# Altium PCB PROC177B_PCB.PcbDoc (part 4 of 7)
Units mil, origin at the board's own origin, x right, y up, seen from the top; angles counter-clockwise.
Board outline 4257.98 x 1561.15 mil, 4 copper layers (Top Layer, Int1 (GND), Int2 (PWR), Bottom Layer), stack 63.572 mil thick; 461 components, 307 nets, 1564 pads, 607 vias.
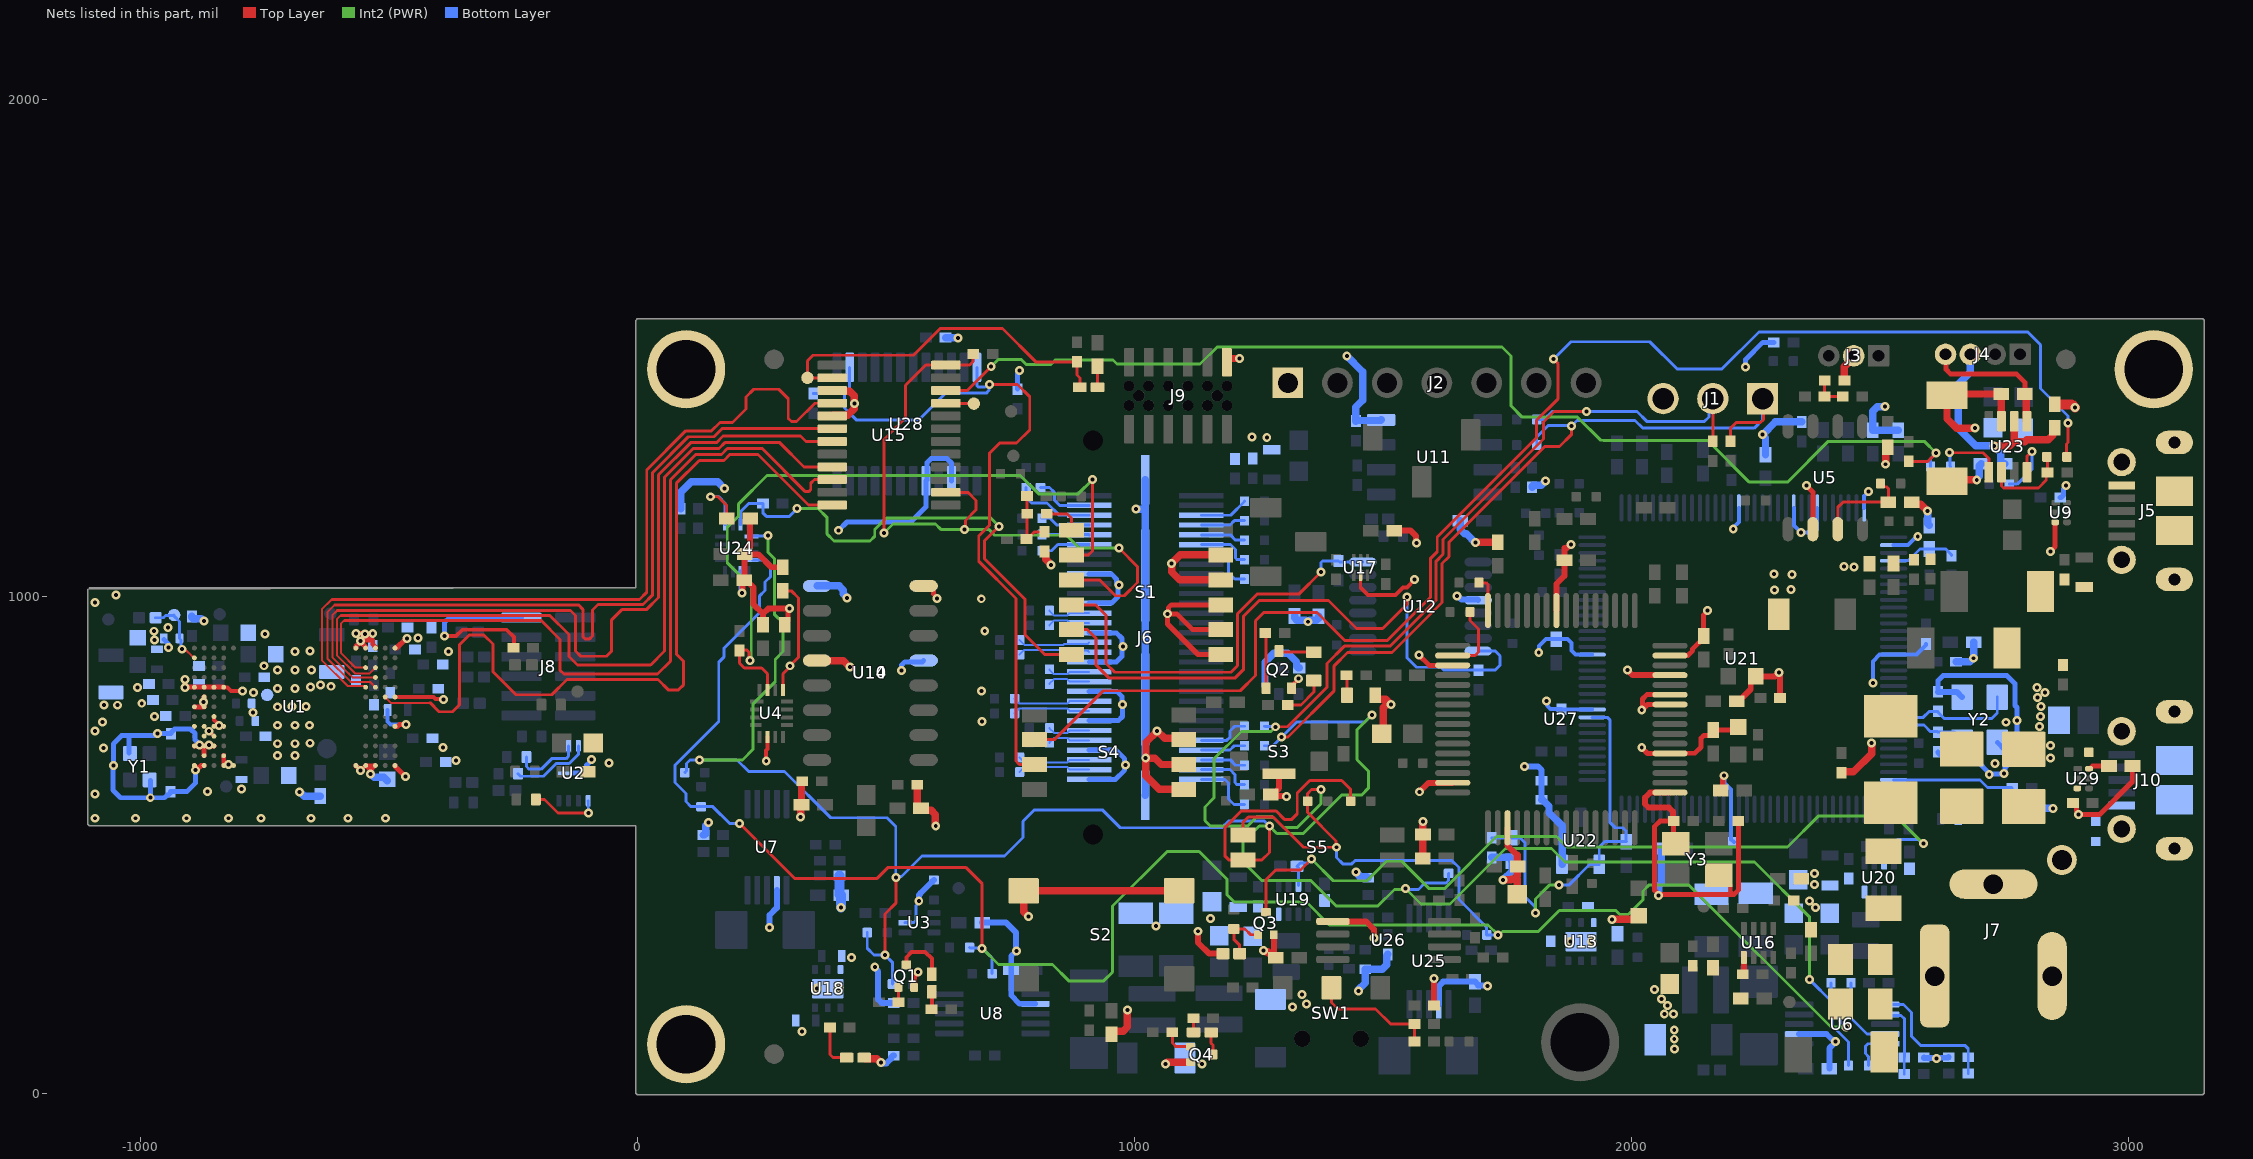
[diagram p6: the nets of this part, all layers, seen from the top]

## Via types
v1: diameter 18, hole 8, Top Layer to Bottom Layer, tented both sides, 603 vias
v2: diameter 19.68, hole 7.87, Top Layer to Bottom Layer, 4 vias

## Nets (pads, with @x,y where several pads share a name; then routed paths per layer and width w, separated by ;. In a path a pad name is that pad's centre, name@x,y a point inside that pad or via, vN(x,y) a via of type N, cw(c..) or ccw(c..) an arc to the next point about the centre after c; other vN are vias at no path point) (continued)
GND: C2.2 C3.1 C4.1 C5.1 C6.2 C7.1 C8.1 C9.1 C10.1 C11.1 C12.1 C13.2 C14.1 C15.2 C16.1 C17.1 C18.1 C19.1 C20.1 C21.1 C22.1 C23.2 C24.1 C25.1 C26.1 C27.1 C28.1 C29.1 C30.2 C31.2 C32.1 C33.1 C34.2 C35.1 C36.2 C37.1 C38.1 C39.1 C40.2 C41.2 C42.2 C43.2 C44.2 C45.2 C46.1 C47.2 C48.2 C49.2 C50.1 C51.2 C52.1 C53.2 C55.2 C56.2 C57.2 C58.2 C59.2 C60.1 C61.1 C62.2 C63.2 C65.2 C66.2 C67.2 C68.1 C69.1 C70.1 C72.2 C73.2 C74.2 C75.2 C79.1 C84.2 C85.1 C86.1 C88.2 C89.2 C90.2 C91.2 C92.2 C93.2 C94.2 C95.1 C96.1 C97.1 C98.1 C99.1 C101.1 C102.1 C105.1 C106.1 C108.2 C113.1 C114.2 C115.2 C116.1 C118.1 C119.2 C120.2 C121.1 C122.1 C123.2 C124.1 C125.1 C126.1 C127.2 C128.2 C129.2 C130.1 C131.1 C132.2 C133.2 C134.2 C135.2 C136.2 C137.2 C138.2 C139.2 C140.2 C141.2 C142.1 C143.2 C144.2 C145.2 C146.1 C147.2 C148.2 C149.1 C150.2 C151.1 C152.2 C153.2 C157.2 C158.2 D4.2 D6.2 D10.2 J1.3 J2.1 J3.2 J4.4 J5.5 J5.6 J5.7 J5.8 J5.9 J5.10 J5.11 J6.18 J6.24 J6.30 J6.36 J6.42 J6.48 J6.54 J6.60 J6.MP1 J6.MP2 J6.MP3 J6.MP4 J7.2 J7.3 J8.11 J9.12 J10.5 pad.TH1 pad.TH4 pad.TH9 Q1.2 Q2.2 Q3.2 Q4.2 R6.1 R10.2 R11.1 R33.1 R36.1 R57.2 R71.1 R72.1 R83.1 R91.2 R101.1 R103.1 R113.1 R114.1 R116.1 R117.1 R120.1 R121.1 R148.1 R150.1 R152.2 R158.1 R162.1 R177.1 R178.1 R180.1 R191.2 R194.2 R201.1 R205.1 R208.1 R215.2 R218.1 R234.1 R239.1 R260.1 R261.1 S1.7 S1.8 S1.9 S1.10 S1.11 S2.1 S2.2 S3.5 S4.5 S4.6 S4.7 TP7.1 TP11.1 U1.A1 U1.A3 U1.A4 U1.A5 U1.A6 U1.A7 U1.A9 U1.A10 U1.B7 U1.B9 U1.C8 U1.C9 U1.C10 U1.D8 U1.D9 U1.E1 U1.E7 U1.E8 U1.E9 U1.E10 U1.F8 U1.G9 U1.G10 U1.H1 U1.H9 U1.J7 U1.J8 U1.J9 U1.J10 U1.N1 U1.N3 U1.N4 U1.N5 U2.4 U2.9 U3.2 U4.6 U5.2 U6.7 U7.7 U8.7 U9.3 U10.8 U10.12 U11.4 U12.4 U13.3 U13.7@1898.8,304.92 U14.8 U14.12 U15.3 U15.5 U16.1 U17.2 U18.3 U18.7@383.33,210.5 U19.8 U20.8 U21.10 U21.17 U21.48 U21.55 U21.58 U21.64 U21.66 U21.80 U21.114 U22.2 U23.5 U24.6 U25.7 U26.5 U27.1 U27.5 U27.10 U27.11 U27.13 U27.15 U27.25 U27.35 U27.47 U27.51 U28.3 U28.5 U29.3 Y1.2 Y1.4 Y2.2 Y2.4 Y3.2 Y3.4 | length 14542.7
  Top Layer w5.9: U17.2@1455.43,1041.94 1455.43,1017.67 1456.22,1016.88
  Top Layer w8: v1(-861.2,728.31) U1.D8@-851.36,718.46 ; U1.F8@-851.36,757.83 -851.36,750.77 -841.52,740.92 v1(-841.52,739.83) -840.18,738.5 -832.03,738.5 U1.E7@-831.67,738.15 ; U1.J7@-831.67,816.89 -831.32,816.54 -824.42,816.54 -817.04,809.16 v1(-793.68,809.16) ; v1(-556.53,649.12) U1.A4@-546.24,659.41 ; U1.H1@-487.19,797.2 -409.65,797.2 -405.69,793.25 -390.42,793.25 v1(-389.2,792.03) ; v1@-387.87,917.47 v1(-387.87,919.64) -364.47,919.64 -351.62,932.49 -263.18,932.49 -248.11,917.42 C60.1@-248.11,897.01 ; v1(259.69,668.14) 259.58,668.25 259.58,689.74 261.97,692.13 U4.6@261.97,716.92 ; Q2.2@1316.5,814.83 1321.75,820.08 1321.75,824.25 1329.98,832.47 v1(1329.98,833.94) ; 1456.22,1016.88 1470.64,1002.46 1525.86,1002.46 1540.96,1017.56 1548.51,1017.56 v1(1564.15,1033.2) ; Y3.2@2176,438.61 2179.94,438.61 2199.56,418.99 2199.56,406.22 2206.17,399.6 ; U1.A4@-546.24,659.41 -546.24,658.91 -538.26,650.93 -538.26,644.01 v1(-536.35,642.1) -534.43,644.01 -534.43,651.03 -526.56,658.91 U1.A3@-526.56,659.41 U1.A4@-546.24,659.41
  Top Layer w10: v1(-909.63,816.66) v1(-909.63,832.61) v1@-909.63,833.61 ; v1@-907.96,816.89 U1.J10@-890.73,816.89 U1.J9@-871.04,816.89 U1.J8@-851.36,816.89 U1.J7@-831.67,816.89 ; U1.A10@-890.73,659.41 -889.45,658.13 -889.45,651 v1(-888.3,649.85) -886.68,649.85 -877.12,659.41 U1.A9@-871.04,659.41 ; U1.G10@-890.73,777.52 U1.G9@-872.73,777.52 ; U1.C10@-887.52,699.03 -890.48,699.03 U1.C10@-890.73,698.78 U1.C9@-871.04,698.78 ; U1.B9@-871.04,679.09 U1.C9@-871.04,698.78 ; U1.G9@-871.04,777.52 -871.58,778.06 -871.58,786.21 v1(-872.73,787.36) -871.58,788.51 -871.58,796.67 U1.H9@-871.04,797.2 ; U1.C8@-851.36,698.78 U1.C9@-871.04,698.78 ; U1.A7@-831.67,659.41 U1.B7@-831.67,679.09 ; U1.A5@-565.93,659.41 -556.53,650.01 v1(-556.53,649.12) ; U1.N5@-565.93,895.63 -565.93,898.72 v1@-557.22,907.43 ; v1(-565.95,925.04) -565.53,924.62 -548.35,924.62 v1(-547.94,924.2) -547.94,922.58 -544.91,919.56 -544.91,919.49 -536.8,911.38 ; v1@-558.07,907.43 v1@-557.22,907.43 ; v1(-556.55,909.72) -556.55,908.09 v1@-557.22,907.43 ; -547.09,911.38 -536.8,911.38 ; U1.N4@-546.24,895.63 -546.24,897.78 -555.89,907.43 v1@-557.22,907.43 ; -532.41,911.38 -536.8,911.38 ; -531.91,911.38 -531.91,903.25 -526.56,897.89 U1.N3@-526.56,895.63 ; U1.A1@-487.19,659.41 -487.19,657.88 -466.92,637.61 v1(-465.65,637.61) ; U1.E1@-487.19,738.15 -481.89,738.15 -478.61,741.43 -465.08,741.43 v1(-464.61,741.9) ; U1.N1@-487.19,895.63 -483.99,895.63 -465.61,914.01 -463.89,914.01 v1(-462.74,915.16) ; C40.2@296.84,942.57 303.65,949.38 303.65,969.86 306.55,972.77 v1(306.55,974.93) ; U14.8@576.39,1020.53 589.44,1020.53 595.73,1014.24 595.73,1004.78 602.81,997.7 v1(602.81,995.53) ; S1.7@1173.96,882.62 1128.38,882.62 1067,944 v1(1067,964.6) ; S1.8@1173.96,932.62 1117.38,932.62 1085.55,964.45 1067.15,964.45 v1(1067,964.6) ; S1.9@1173.96,982.62 1074.64,982.62 1068.53,976.5 1068.53,966.13 v1(1067,964.6) ; v1(1572.8,881.36) 1593.32,860.84 U27.35@1640.61,860.84 ; v1(2020.94,695.16) 2032.44,683.67 U27.5@2077.62,683.67 2077.96,684.02 2127.65,684.02 2140.31,696.68 2140.31,714.24 2146.17,720.1 2157.93,720.1 2164.74,726.91 C142.1@2164.74,730.84 2208.84,730.84 C141.2@2214.74,736.75 ; v1(2020.94,770.6) v1@2022.44,772.1 ; U27.10@2077.62,782.1 2032.44,782.1 v1@2022.44,772.1 ; U27.11@2077.62,801.78 2031.18,801.78 2022.44,793.04 v1@2022.44,772.1 ; U27.15@2077.62,880.52 2077.96,880.87 2113.93,880.87 2123.39,890.33 2123.39,893.92 2145.41,915.94 C140.2@2145.41,919.88 2145.41,962.63 v1(2153.65,970.87) ; Y3.4@2089.38,501.6 2085.23,505.75 C148.2@2085.23,547.51 2057.66,547.51 2047.03,536.88 2047.03,408.16 2055.06,400.13 v1(2055.06,398.3) 2056.36,399.6 2206.17,399.6 2215.12,408.54 C147.2@2215.12,547.51 ; v1(2352,1222.6) 2365.27,1209.33 U5.2@2365.27,1134.88 ; J4.4@2632.04,1486.59 2633.21,1485.42 2633.21,1455.92 2642.38,1446.75 2775.16,1446.75 2791.62,1430.29 C123.2@2791.62,1406.74 ; v1(2843,1089.6) 2843,1089.74 2852.72,1099.46 U9.3@2852.72,1148.57 ; R260.1@2888.29,584.07 2890.26,584.07 2895.1,579.23 2895.1,567.49 2899.47,563.12 v1(2899.47,560.95) 2941.95,560.95 3008.27,627.27 C158.2@3008.27,658.22
  Top Layer w12: v1(210.65,1006.68) 211.8,1007.83 211.8,1028.39 C2.2@215.41,1032 ; R33.1@227.35,1156.14 227.35,1097.45 225.9,1096 225.9,1090.42 220.09,1084.61 C56.2@216.15,1084.61 ; C91.2@253.09,942.57 253.09,964.32 ; R6.1@293,1058.22 269.93,1058.22 244.42,1083.73 217.03,1083.73 C56.2@216.15,1084.61 ; v1(306.55,974.93) 263.7,974.93 253.09,964.32 ; Q1.2@557.18,212.97 557.18,235.84 565.26,243.91 v1(565.26,244.19) ; v1(1128.09,325.95) 1128.09,303.33 1150.55,280.87 R177.1@1178.5,280.87 ; C138.2@1281.06,276.91 Q3.2@1281.06,318.65 ; S3.5@1291.37,642.9 1291.37,613.97 1278.24,600.84 R215.2@1274.3,600.84 1276.99,598.15 1305.42,598.15 v1(1306.56,597) ; U26.5@1399.58,345.78 1466.13,345.78 1481.98,329.94 v1(1481.98,311.94) ; C52.1@1522.83,1131.87 1556.02,1131.87 1566.59,1121.31 1566.59,1107.8 v1(1567.74,1106.65) ; v1(1573.94,606.54) 1592.01,624.62 U27.47@1640.61,624.62 ; v1(1602.6,230.66) 1602.85,230.41 1602.85,176.85 R205.1@1603.1,176.6 ; U27.51@1750.84,534.06 1750.94,533.97 1750.94,498.09 1770.18,478.84 ; C150.2@1770.18,457.3 C150.2@1771.42,456.06 ; U27.25@1849.27,971.07 1849.27,1024.64 1865.44,1040.8 C153.2@1865.44,1072.47 1865.44,1097.27 1870.24,1097.27 1876.86,1103.9 v1(1878.49,1103.9) ; v1(1992,851.6) 2002.45,841.15 U27.13@2077.62,841.15 ; U27.1@2077.62,604.93 2077.52,604.84 2037.54,604.84 2027.38,594.68 2027.38,581.89 2034.45,574.82 2075.53,574.82 2083.69,566.66 2083.69,549.05 C148.2@2085.23,547.51 ; C106.1@2179.82,608.87 2183.9,612.95 2183.9,634.27 2186.8,637.17 v1(2186.8,638.8) ; C146.1@2212.15,788.54 2216.09,788.54 2240.2,812.65 2240.2,829.1 C145.2@2249.95,838.85 2288.62,838.85 v1(2296.66,846.89) 2296.66,845.26 2299.28,842.64 R218.1@2299.28,794.95 ; C136.2@2224.31,239.6 2226.38,241.67 2226.38,273.37 U16.1@2226.47,273.47 ; C2.2@215.41,1032 219.35,1032 234.34,1017.01 234.34,983.06 253.09,964.32 ; C2.2@215.41,1032 216.15,1032.74 215.78,1033.11 215.78,1084.24 C56.2@216.15,1084.61
  Top Layer w15: v1(328.94,555.46) 329.51,556.04 329.51,579.22 C89.2@330.57,580.27 330.57,626.49 C90.2@331.88,627.8 ; U14.12@361.83,870.53 414.26,870.53 427.19,857.6 v1(428,857.6) ; U15.5@392.51,1362.51 393.87,1363.87 423.2,1363.87 436.46,1377.14 436.46,1387.03 v1(437.03,1387.6) ; U15.3@392.51,1413.69 393.87,1412.34 427.67,1412.34 436.46,1403.55 v1@436.46,1388.06 ; D6.2@456.79,71.69 459.14,69.35 482.1,69.35 489.37,62.08 v1(490.18,62.08) ; C88.2@563.4,620.74 563.4,577.86 567.71,573.55 C75.2@570.88,573.55 575.19,569.24 591.32,569.24 600.11,560.45 600.11,538.15 v1(600.68,537.57) ; v1(787,355.6) 777.5,365.1 S2.1@777.5,407.18 S2.2@1090.49,407.18 ; R208.1@819.66,1090.02 822,1087.68 822,1074.04 832.18,1063.86 v1(832.18,1063.05) ; C53.2@954.88,121.37 958.31,124.8 977.56,124.8 986.34,133.59 v1@986.34,166.55 ; v1(1062.6,58.83) 1063.41,58.83 1066.83,62.25 Q4.2@1113.28,62.25 ; v1(1075.32,1065.6) 1075.32,1048.68 1091.38,1032.62 S1.10@1173.96,1032.62 ; v1@1075.62,1065.9 1092.72,1083 1173.57,1083 S1.11@1173.96,1082.62 ; S4.5@1099.68,611.36 1050.31,611.36 1023.1,638.58 v1(1023.1,674.39) ; S4.6@1099.68,661.36 1054.14,661.36 1041.68,673.82 1023.68,673.82 v1(1023.1,674.39) ; S4.7@1099.68,711.36 1096.59,714.45 1060.97,714.45 1046.81,728.6 v1(1046,728.6) 1023.68,706.28 1023.68,674.97 v1(1023.1,674.39) ; J9.12@1186.47,1476.71 1187.9,1478.15 v1(1212.01,1478.15) ; v1(1260.17,287.48) 1260.98,287.48 1264.04,284.41 1268.63,284.41 1276.13,276.91 1280.07,276.91 C138.2@1284.38,272.6 ; D10.2@1484.95,800.77 1484.95,796.83 1489.26,792.52 1505.79,792.52 v1@1511.7,786.61 ; C151.1@1497.62,723.04 1500.67,726.1 1500.67,775.58 v1@1511.7,786.61 ; v1(1516.26,782.05) v1@1511.7,786.61 ; v1(1580.68,546.28) v1(1580.68,546.28) 1580.73,520.82 C143.2@1580.78,520.77 1580.7,520.69 C144.2@1580.7,472.42 ; v1(1686.78,1107.74) 1687.59,1107.74 1688.17,1108.32 C152.2@1731.16,1108.32 ; v1(1742.05,429.4) 1742.62,429.98 1757.84,429.98 1758,430.13 1770.07,430.13 C149.1@1770.07,400.73 ; C150.2@1770.18,457.3 1770.18,478.84 ; 1770.74,436.17 1770.74,455.39 C150.2@1771.42,456.06 ; v1(1961.35,349.63) 1961.92,350.2 2008.07,350.2 C139.2@2015.1,357.24 ; C108.2@2425,644.92 2426.58,646.5 2446.89,646.5 2483.27,682.88 v1(2483.27,704.22) ; C39.1@2428.68,1433.6 2428.68,1461.7 2446.72,1479.73 J3.2@2446.72,1483.05 ; v1(2511.14,1265.41) 2511.71,1265.99 2511.71,1295.86 C38.1@2515.6,1299.75 ; C37.1@2564.2,1189.11 2568.51,1184.8 2582.47,1184.8 v1@2595.01,1172.26 ; C123.2@2791.62,1406.74 2794.52,1403.84 2794.52,1352.96 U23.5@2795.88,1351.6
  Top Layer w20: C132.2@2851.75,1386.02 2885.9,1386.02 v1(2892.5,1379.42)
  Bottom Layer w5.9: U3.2@538.95,343.01 539.83,343.88 556.75,343.88 561,348.13 561,377.8 566.53,383.33 v1(566.53,386.58)
  Bottom Layer w8: C17.1@-501.85,770.72 -501.85,747.52 -495.76,741.43 -465.08,741.43 v1(-464.61,741.9) ; U24.6@208.28,1049.18 208.28,1011.76 210.65,1009.39 v1(210.65,1006.68) ; v1(1813.74,886.39) 1814.43,887.08 1814.43,899.41 1828.64,913.62 C116.1@1848.96,913.62 1871.95,913.62 1879.81,905.76 1879.81,890.35 1887.77,882.39 U21.17@1921.25,882.32 U21.17@1921.25,882.32 ; v1(1829.35,789.39) 1831.26,787.48 1831.26,778.78 1837.47,772.58 C115.2@1859.31,772.58 ; C115.2@1859.8,772.09 U21.10@1921.25,772.09 ; v1(2186.8,638.8) 2187.8,637.8 2187.8,624.2 2200.78,611.22 U21.114@2200.78,571.3 U21.114@2200.78,571.3 2200.84,510.99 C127.2@2206.38,505.45 ; v1(2205,1135.24) 2205,1137.95 2216.46,1149.41 2216.46,1177.54 U21.48@2216.52,1177.6 ; U21.55@2326.76,1177.6 2326.76,1142.34 v1(2341.3,1127.81) 2367.78,1127.81 2374,1134.03 U21.58@2374,1177.6 ; U21.64@2468.49,1177.6 2468.49,1201.1 2477.04,1209.65 v1(2477.04,1210.93) ; v1(2485.7,825.75) 2485.7,868.39 2499.63,882.32 U21.80@2527.55,882.32 2573.49,882.32 2592.89,901.72 C114.2@2592.89,903.69 ; U21.66@2527.55,1102.8 2527.61,1102.86 2556.26,1102.86 2573.85,1120.45 v1(2576.18,1120.45)
  Bottom Layer w10: Y1.2@-1022.21,684.49 -1022.21,718.84 ; Y1.4@-978.9,629.37 -979.18,629.09 -979.18,594.81 v1(-979.47,594.53) ; C3.1@-952.26,913.14 -944.15,905.03 -944.15,898.45 v1(-942.62,896.92) ; v1(-888.3,649.85) -888.3,624.35 -905.99,606.66 C33.1@-938.64,606.66 -938.64,604.7 -943.49,599.85 -945.46,599.85 -950.78,594.53 v1(-979.47,594.53) ; v1@-880.46,698.7 -880.46,701.76 -889.27,710.57 -889.27,723.62 -898.55,732.89 -930.43,732.89 -937.91,725.42 C32.1@-937.91,723.45 -938.43,723.97 v1(-965.07,723.97) -966.69,723.97 -971.37,719.29 -1037.34,719.29 -1053.85,702.79 v1(-1053.85,659.78) -1054.79,658.84 -1054.79,609.98 -1039.34,594.53 v1(-979.47,594.53) ; v1(-387.87,919.64) -387.47,920.03 -387.47,947.64 -378.23,956.88 J8.11@-232.85,956.88 ; U2.9@-128.06,643.83 -102.63,643.83 -101.56,644.89 -101.56,659.95 -91.45,670.07 v1(-91.45,671.69) ; v1(404.9,1132.6) 405.71,1132.6 422.19,1149.07 550.46,1149.07 581.03,1179.65 U28.5@581.03,1232.02 583.04,1234.03 583.04,1268.47 591.17,1276.6 623.42,1276.6 632.21,1267.82 U28.3@632.21,1232.02 ; v1(532,850.6) 532,861.6 538.32,867.92 573.79,867.92 U10.12@576.39,870.53 ; R91.2@765.35,1416.41 765.35,1448.12 768.78,1451.55 v1(768.78,1453.71) ; J6.60@909.41,631.37 962.06,631.37 980.64,649.95 980.64,658.82 v1@980.78,658.96 ; J6.54@909.41,690.42 963,690.42 980.65,672.77 980.65,659.09 v1@980.78,658.96 ; J6.48@909.41,749.48 968.02,749.48 976.37,757.83 976.37,781.53 v1(976.67,781.83) 975.14,783.36 975.14,798.46 965.07,808.53 J6.42@909.41,808.53 ; J6.30@909.41,926.64 909.91,926.15 964.04,926.15 975.45,914.74 975.45,899.59 v1@976.47,898.56 ; J6.24@909.41,985.7 909.91,986.19 954.54,986.19 967.57,999.22 967.57,1021.22 v1(969.1,1022.75) ; J6.18@909.41,1044.75 909.91,1044.26 954.54,1044.26 964.1,1034.7 v1@964.1,1023.15 ; J6.36@909.57,867.75 964.1,867.75 975.45,879.1 975.45,897.03 v1(976.98,898.56) ; v1@981,658.74 v1@980.78,658.96 ; v1(982.17,660.35) v1@980.78,658.96 ; v1(2230,1460.62) 2230,1476.11 2264.4,1510.51 R71.1@2286.59,1510.51 ; C97.1@2616.98,687.07 2616.98,685.1 2621.82,680.26 2630.97,680.26 2647.89,663.34 2700.73,663.34 2707.8,656.27 2707.8,655.97 2720,643.77 v1(2720,641.6) 2720.92,642.52 2749.08,642.52 v1(2750,643.44) 2751.53,644.97 2751.53,655.5 2775.84,679.81 ; C98.1@2616.98,807.64 2616.98,829.96 2627.42,840.41 2755.33,840.41 2771.86,823.88 2771.86,779.98 2775.84,776 v1(2775.84,749.99) 2775.84,679.81 ; Y2.2@2736.13,705.86 2752.78,689.2 2766.44,689.2 2775.84,679.81 ; R72.1@2862.68,1198.6 2864.65,1198.6 2869.49,1203.44 2869.49,1215.73 2874.5,1220.73 v1(2874.5,1222.89)
  Bottom Layer w11: v1(762.76,286.62) 752.17,276.03 C59.2@752.17,249.69 752.17,197.42 769.58,180 800.87,180 U8.7@801.28,179.6
  Bottom Layer w12: v1(266.67,333.78) 266.67,358.69 280.99,373.01 U7.7@280.99,408.58 ; v1(478,253.6) 478,251.98 484.7,245.28 484.7,188.63 491.73,181.6 R116.1@516.31,181.6 ; v1(490.18,62.08) 491.81,62.08 494.09,59.8 498.18,59.8 498.5,60.12 501.62,60.12 510.5,69 510.5,71.76 514.34,75.6 R117.1@516.31,75.6 ; v1(566.53,386.58) 566.53,398.47 570.04,401.99 570.04,402.55 593.16,425.66 593.65,425.66 R57.2@597,429.01 ; C36.2@694.1,343.24 742.36,343.24 762.45,323.15 762.45,286.93 v1(762.76,286.62) ; U25.7@1612.64,178.95 1612.73,179.05 1612.73,215.63 1621.49,224.39 C133.2@1685.69,224.33 1691.51,218.58 1691.51,216.72 1709.36,216.72 v1(1710.51,215.57) ; v1(1649.3,1000.62) 1650.93,1000.62 1658.58,992.97 1690.86,992.97 U12.4@1691.95,991.87 ; v1(1785,657.6) 1812.28,657.6 1819.31,650.57 C118.1@1819.31,628.6 R239.1@1819.31,590.6 ; U6.7@2337.55,119.36 2392.62,119.36 2409.92,102.06 v1@2410.17,102.06 ; C57.2@2398.39,49.43 2398.39,90.28 v1@2410.17,102.06 ; v1@2410.45,102.06 v1@2410.17,102.06 ; v1(2410.45,103.96) 2410.45,102.34 v1@2410.17,102.06 ; R101.1@2588.39,71.79 2589.12,71.06 2613.37,71.06 v1(2614.09,70.33) 2615.23,71.47 2637.18,71.47 R103.1@2638.31,72.6 ; C98.1@2616.98,807.64 2654.39,807.64 Y2.4@2665.26,796.76
  Bottom Layer w15: C11.1@-895.64,959.28 -895.64,957.31 -893.3,954.96 -876.52,954.96 -872.06,950.51 v1(-871.25,950.51) ; v1(-679.08,606.42) -678.27,606.42 -669.74,597.89 C31.2@-641.85,597.89 ; C31.2@-641.84,597.88 C31.2@-637.54,597.88 ; v1(-536.35,642.1) -535.53,642.1 -529.29,635.85 -510.02,635.85 C43.2@-502.75,628.59 ; R152.2@87.87,1175.83 87.87,1209.26 108.64,1230.03 162.21,1230.03 v1(175.78,1216.45) ; R114.1@133.31,519.6 135.28,519.6 137.62,521.94 137.62,537.97 143.56,543.91 v1(143.56,544.72) ; U10.8@361.83,1020.53 406.2,1020.53 414.99,1011.74 414.99,1004.77 422.45,997.31 v1(422.45,996.5) ; R10.2@620.4,1520.36 620.75,1520.02 644.86,1520.02 v1(645.21,1519.67) ; v1(1003.91,1175.81) 1004.48,1175.24 1016.42,1175.24 1022.21,1169.45 ; J6.MP4@1022.21,599.28 1022.65,599.73 1022.65,673.95 v1(1023.1,674.39) ; v1@1022.21,674.39 J6.MP3@1022.21,791.8 ; J6.MP2@1022.21,1041.8 1022.21,1169.45 ; J6.MP1@1022.21,1234.32 1022.21,1169.45 ; J6.MP3@1022.33,791.92 J6.MP2@1022.33,1041.68 ; 1263,818.6 1263,867.43 1281.03,885.46 1309.29,885.46 1326.42,868.33 1326.42,859.37 1330.19,855.6 R201.1@1331.91,855.6 ; R83.1@1322.56,960.18 1322.56,956.24 1326.87,951.93 1345.07,951.93 1348.45,948.56 v1(1349.26,948.56) 1350.07,948.56 1352.89,951.37 1366.52,951.37 1370.83,955.68 C41.2@1370.83,959.62 ; v1(1427.53,1483.28) 1459.22,1451.59 1459.22,1393.84 1446,1380.61 R162.1@1446,1352.29 1447.09,1353.38 1495.48,1353.38 U11.4@1496.57,1354.47 ; v1(1445.68,445.49) 1445.68,444.68 1451.18,439.18 1451.18,438.27 1453.42,436.03 1468.15,436.03 R148.1@1470.49,433.69 ; v1(1451,205.6) 1451.57,206.18 1451.57,208.87 1464.61,221.91 R121.1@1464.61,249.49 1498.92,249.49 1507.71,258.28 1507.71,277.19 R150.1@1509.86,279.34 ; C65.2@1655.74,1151.54 1655.55,1151.35 1655.55,1134.17 1664.34,1125.38 1668.32,1125.38 1685.97,1107.74 v1(1686.78,1107.74) ; C102.1@1719.12,474.55 1754.81,474.55 1759.12,470.23 C99.1@1759.12,466.67 1759.95,465.84 1759.95,446.78 1742.58,429.4 v1(1742.05,429.4) ; R158.1@1800.31,1218.98 1800.31,1220.95 1802.65,1223.29 1818.4,1223.29 1826.78,1231.67 v1(1827.6,1231.67) ; R239.1@1819.31,590.6 1821.28,590.6 1834.37,577.51 1834.37,564.71 1860.6,538.48 U22.2@1860.6,460.36 ; v1(2055.06,398.3) 2055.06,417.88 2060.59,423.41 C126.1@2060.59,491.78 ; C113.1@2269.89,1284.61 2269.89,1319.02 v1(2263.96,1324.95) 2289.46,1350.45 R234.1@2342.87,1350.45 ; v1(2509.99,1381.85) 2509.42,1381.28 2494.41,1381.28 2485.43,1372.29 R194.2@2485.43,1334.05 R191.2@2536.85,1334.05 ; v1(2595.58,1171.69) 2596.15,1171.11 2596.15,1145.56 C95.1@2599.45,1142.27 ; C124.1@2653.16,868.02 2681.27,868.02 v1(2688.39,875.14) 2688.58,875.33 2688.58,907.35 C125.1@2688.76,907.54 ; C94.2@2809.62,575.6 2811.69,573.53 2847.65,573.53 v1(2848.23,572.96)
  Bottom Layer w20: R113.1@407.13,437.96 407.13,400.28 408.94,398.47 C58.2@410.33,398.47 410,398.14 v1(410,373.66)
  other v1: 1136.72,58.83 2086.58,89.29 2086.29,108.71 331.71,124.08 2086.29,127.38 2084.78,159.31 2066.24,159.38 986.01,167.7 1318.49,173.5 2072.66,176.22 1346.91,179.69 2060.35,189.28 1337.75,198.87 2046.47,209.1 430.99,273.1 1043.93,336.4 1153.63,351.18 2370.28,373.65 2358.12,386.92 2368.89,420.19 2368.89,442.01 -1090.48,553.27 -1009.45,553.27 -906.45,553.27 -821.65,553.27 -756.45,553.27 -656.45,553.27 -581.45,553.27 -506.45,553.27 -1090.34,601.79 -864.74,606.79 -795.81,612.35 -821.83,661.09 2731.61,663.48 -56.95,664.44 -364.45,669.83 2842.78,674.9 -723.29,679.18 -687.99,679.49 -1073.63,694.33 -390.63,695.74 2843.1,699.76 -880.46,700.71 -861.2,700.46 -723.83,703.19 -687.96,703.19 -658.22,704.18 -1090.35,728.54 2821.05,738.19 -723.83,740.35 -687.96,740.35 -659.49,740.35 -1075.12,746.79 2753.9,746.4 693.57,747.88 -971,757.6 2823.51,758.23 -772.81,766.42 -723.83,777.52 -694.51,777.81 -666.47,778.05 2823.89,777.88 -1045.29,780.62 -1072.55,781.48 -996.59,784.58 2816.86,796.3 -772,806.38 2832.1,806.68 692.96,809.3 -723.83,814.68 -687.96,814.68 2815.69,815.89 -1005.12,816.7 -657.49,817.54 -615.52,818.76 -637.14,820.87 -723.83,851.85 -687.96,851.85 -655.08,851.85 -750.57,860.01 -687.96,889.02 -379.88,888.44 -658.22,889.46 -971.27,911.5 -440.76,915.98 -748.67,923.91 -531.91,924.87 -971.73,929.5 699.27,930.18 -943.88,936.64 -1090.73,986.94 692.25,994.81 -1048.85,1002.61 2288.29,1012.77 2321.56,1013.26 2322.81,1044.04 2287.05,1045.03 2448.23,1058.99 2427.72,1059.49 1266.57,1319.13 1236.5,1319.9
  other v2: 361.68,210.5 404.99,210.5 1877.15,304.92 1920.46,304.92
GPADC1: C3.2 R86.1 TP6.1 U1.M10 | length 147
  Top Layer w4: v1(-915.77,893.27) -913.48,890.97 -907.54,890.97 -895.34,878.77 -895.14,878.77 -892.31,875.94 U1.M10@-890.73,875.94
  Bottom Layer w5.9: R86.1@-968.51,956.6 -953.51,956.6 -948.98,961.13 -932.33,961.13 TP6.1@-931.35,962.11 -931.35,959.69 -920.76,949.11 C3.2@-920.76,915.11 -917.71,912.05 -917.71,895.2 v1(-915.77,893.27)
HOST_CLK: TP4.1 U15.21 | length 56.8
  Top Layer w5.9: U15.21@620.85,1388.1 621.7,1387.25 TP4.1@677.26,1387.25
HOSTIRQ_FTDI_IN: R216.1 U27.32 | length 71.9
  Top Layer w5.9: R216.1@1693.52,1027.4 1694.07,1026.85 1707.96,1026.85 1711.47,1023.34 U27.32@1711.47,971.07
HOSTIRQ_FTDI_OUT: R217.1 U27.34 | length 142.9
  Top Layer w5.9: U27.34@1640.61,880.52 1685.87,880.52 1692.8,887.46 1692.8,933.78 1675.52,951.06 R217.1@1675.52,968.12
I2C_SCL: J1.1 R25.2 R56.1 R60.1 R97.1 R108.2 R109.2 R137.2 R159.2 R199.1 S5.2 U24.1 | length 7079.3
  Top Layer w5.9: v1(498.56,278.44) 498.56,360.56 520.36,382.36 v1(520.36,433.93) ; v1(1271.86,537.73) 1271.86,484.53 1256.93,469.6 S5.2@1219,469.6 1190,469.6 1182.88,476.72 1182.88,535.3 1215.15,567.58 1285.53,567.58 1301.93,551.17 1316.8,551.17 1327.92,562.29 1327.92,603.79 1353.24,629.11 1417.27,629.11 1435.37,611.01 R199.1@1435.37,587.64 ; v1@1296.5,716.62 1296.74,716.85 1309.05,716.85 1402.17,809.97 1402.17,859.96 1428.83,886.63 1518.61,886.63 1619.33,987.35 1619.33,1065.54 1633.29,1079.5 1633.29,1108.46 1825.81,1300.99 1855.54,1300.99 1879.3,1324.74 v1(1879.3,1342.2) ; R97.1@2199.73,1312.27 2199.73,1338.04 2210.83,1349.14 2259.91,1349.14 2265.82,1355.04 2265.82,1395.54 J1.1@2263.91,1397.45
  Int2 (PWR) w5.9: v1(125.26,670.6) 211.73,670.6 233.43,692.31 233.43,783.58 277.77,827.92 277.77,872.9 293.46,888.59 293.46,945.8 276.7,962.57 276.7,1074.66 262.99,1088.37 v1(262.99,1122.25) ; v1(1478.17,761.3) 1448.24,731.37 1448.24,671.06 1470.95,648.35 1470.95,613.56 1457.1,599.71 1417.1,599.71 1340.1,522.71 1286.87,522.71 v1(1271.86,537.73) 1251.59,537.73 1218.74,504.87 1218.74,465.76 1256.15,428.34 1354.66,428.34 1405.84,377.16 1490.28,377.16 1523.27,410.15 1544.27,410.15 v1(1545.85,411.73) 1576.87,380.72 1635.18,380.72 1746.96,492.5 1839.53,492.5 1866.55,465.48 2247.6,465.48 2358.77,354.31 v1(2358.77,228.56)
  Bottom Layer w5.9: R108.2@95.83,644.91 99.36,648.44 99.36,663.6 106.37,670.6 v1(125.26,670.6) 200.95,670.6 224.52,647.03 296.66,647.03 389.44,554.25 502.47,554.25 520.21,536.51 v1@520.21,434.07 ; U24.1@229.93,1120.04 230.92,1121.03 261.78,1121.03 v1(262.99,1122.25) ; R56.1@462.87,323.15 462.87,291.84 476.28,278.44 v1(498.56,278.44) 513.38,263.62 R109.2@513.38,219.86 ; v1(520.36,433.93) 522.24,435.81 531.92,435.81 573.27,477.16 739.16,477.16 776.44,514.44 776.44,547.14 799.55,570.25 935.75,570.25 971.79,534.21 1175.86,534.21 1189.64,547.98 1261.6,547.98 v1(1271.86,537.73) ; R60.1@1262.19,699.12 1279,699.12 v1(1296.17,716.29) 1326.74,746.86 1463.73,746.86 v1(1478.17,761.3) ; v1(1545.85,411.73) 1547.4,410.19 1571.66,410.19 1584.09,422.62 1627.08,422.62 1632.24,427.79 1632.24,441.78 R137.2@1632.66,442.2 ; R159.2@1809.65,1304.1 1809.65,1320.22 1832.69,1343.26 1878.24,1343.26 v1(1879.3,1342.2) 1890.73,1353.64 2007.53,1353.64 2023.27,1337.9 2247.14,1337.9 2263.79,1354.55 2263.79,1397.32 J1.1@2263.91,1397.45 ; v1(2358.77,228.56) 2403.59,183.74 2403.59,136.21 2436.82,102.98 R25.2@2436.82,55.6
I2C_SDA: J1.2 R29.2 R55.1 R59.1 R98.1 R110.2 R111.2 R139.2 R160.2 R197.1 S5.1 U24.4 | length 6788.4
  Top Layer w5.9: v1(205.77,543.12) 316.5,432.38 482.92,432.38 505.06,454.52 660.92,454.52 694.13,421.31 v1(694.13,291.66) ; S5.1@1219,519.6 1219,545.15 1229.52,555.68 1279.76,555.68 1300.55,534.88 1340.5,494.93 v1(1406.92,494.93) 1406.08,495.78 1406.08,507.52 1348.82,564.78 R197.1@1348.82,587.6 1348.82,603.21 1356.77,611.16 v1(1375.32,611.16) ; v1(1284.54,737.28) 1308.39,737.28 1387.87,816.77 1387.87,864.69 1422.53,899.35 1514.5,899.35 1607.43,992.28 1607.43,1070.47 1621.39,1084.43 1621.39,1114.08 1823.46,1316.16 1823.46,1350.68 1844.37,1371.59 v1(1910.02,1371.59) ; R98.1@2163.94,1311.54 J1.2@2163.94,1397.41
  Int2 (PWR) w5.9: v1(694.13,291.66) 726.88,258.91 835.59,258.91 868.22,226.28 938.7,226.28 956.1,243.68 956.1,376.49 1066.22,486.62 1130.56,486.62 1187,430.18 1187,398.83 1201.23,384.6 1346.43,384.6 1392.47,338.57 1711.8,338.57 v1(1731.53,318.84) 1734.48,318.84 1741.03,325.4 1812.86,325.4 1855.04,367.58 1968.78,367.58 1976.67,359.69 1993.83,359.69 2023.48,389.33 2023.48,406.98 2035.8,419.29 2115.15,419.29 2401.39,133.05 v1(2432.13,133.05) ; v1(1284.54,737.28) 1284.29,737.28 1275.04,728.03 1215.84,728.03 1160.63,672.82 1160.63,594.41 1142.12,575.89 1142.12,548.33 1153.17,537.29 1227.82,537.29 1246.21,555.68 1279.3,555.68 1300.36,534.61 1328.09,534.61 1375.32,581.85 v1(1375.32,611.16)
  Bottom Layer w5.9: v1(205.77,543.12) 185.51,543.12 152.16,576.47 R110.2@128.61,576.47 108.52,576.47 98.09,586.9 98.09,603 76.12,624.98 76.12,659.87 164.08,747.84 164.08,867.2 175.11,878.22 175.11,895.77 245.74,966.4 245.74,999.75 257.45,1011.46 257.45,1028.29 268.67,1039.51 268.67,1063.92 259.79,1072.8 U24.4@231.9,1072.8 ; R55.1@668.82,293.12 669.55,292.39 693.4,292.39 v1(694.13,291.66) ; v1@694.08,292.39 714.18,272.29 R111.2@714.18,240.6 ; R59.1@1262.19,738.31 1262.71,737.8 1284.03,737.8 v1(1284.54,737.28) ; v1(1406.92,494.93) 1406.92,474.16 1419.44,461.65 1437.56,461.65 1443.83,467.92 1639.35,467.92 1653.16,454.11 1653.16,389.55 1708.87,333.84 1708.87,318.9 1709.16,318.62 1709.3,318.72 1731.4,318.72 v1(1731.53,318.84) ; R160.2@1809.65,1355.38 1810.07,1355.8 1824.4,1355.8 1840.18,1371.59 v1(1910.02,1371.59) 2011.28,1371.59 2031.04,1351.83 2147.43,1351.83 2156.16,1360.56 2156.16,1389.7 J1.2@2163.91,1397.45 ; R29.2@2401.72,222.2 2401.72,203.35 2419.29,185.79 2419.29,145.9 v1(2432.13,133.05)
LIN_BUS: C132.1 J4.3 R21.1 U23.6 | length 476.7
  Top Layer w15: v1(2729.45,1302.24) 2761.51,1302.24 2770.29,1311.02 ; U23.6@2770.29,1351.6 2770.29,1311.02 ; C132.1@2851.75,1338.78 2847.44,1334.47 2847.44,1323.77 2838.65,1314.98 2795.46,1314.98 2791.5,1311.02 2770.29,1311.02
  Bottom Layer w15: J4.3@2682.04,1486.59 2682.04,1450.6 2657.94,1426.5 2657.94,1337.45 2693.15,1302.24 2730.11,1302.24 2730.11,1301.42 2743.46,1288.07 2743.46,1270.54 2747.77,1266.23 R21.1@2751,1266.23
LIN_PHY_EN: R17.1 R88.2 U23.2 | length 174.1
  Top Layer w5.9: U23.2@2744.7,1249.24 2744.7,1221.64 2748.55,1217.78 2818.98,1217.78 2834.65,1233.45 2834.65,1246 R17.1@2837.34,1248.69
  Top Layer w6: R88.2@2835.82,1280.21 2837.34,1278.69 R17.1@2837.34,1248.69
LIN_PHY_EN_CTRL: R88.1 S4.2 | length 2923.1
  Top Layer w5.9: S4.2@799.68,711.36 839.13,711.36 937.58,809.81 1213.45,809.81 1243.9,840.26 1243.9,912.58 1243.86,912.61 1243.86,938.88 1243.9,938.92 1243.9,950.36 1260.46,966.92 1367.39,966.92 1397.68,936.63 1423.07,911.25 1509.57,911.25 1595.53,997.2 1595.53,1075.4 1609.49,1089.35 1609.49,1119.01 1809.23,1318.76 1809.23,1353.79 1852.74,1397.3 1852.74,1467.4 1843.79,1476.35 v1(1843.79,1476.91) ; R88.1@2876.18,1280.21 2875.13,1281.25 2875.13,1306.18 2878.56,1309.61 v1(2878.56,1347.97)
  Bottom Layer w5.9: v1(1843.79,1476.91) 1878.71,1511.82 2037.23,1511.82 2091.71,1457.34 2182.49,1457.34 2256.75,1531.6 2797.42,1531.6 2823.33,1505.7 2823.33,1417.92 2878.56,1362.69 v1(2878.56,1347.97)
LIN_PHY_RX: R18.1 R22.1 U15.22 | length 2352.5
  Top Layer w5.9: U15.22@620.85,1413.69 621.09,1413.45 663.77,1413.45 v1(712.29,1461.98) ; R22.1@2558.1,1271.22 R22.1@2558.1,1271.22 2596.63,1271.28 2613.07,1287.72 v1(2613.07,1288.04)
  Int2 (PWR) w5.9: v1@712.45,1462.14 726.6,1476.28 772.72,1476.28 782.51,1466.49 832.35,1466.49 840.89,1475.04 957.13,1475.04 965.26,1466.91 1132.23,1466.91 1166.81,1501.49 1739.68,1501.49 1757.99,1483.19 1757.99,1382.91 1780.75,1360.15 1891.83,1360.15 1938.34,1313.63 1944.04,1313.63 2153.18,1313.6 2237.4,1229.38 2313.96,1229.38 2396.14,1311.57 2589.22,1311.57 2612.75,1288.04 v1(2613.07,1288.04)
  Bottom Layer w5.9: R18.1@2601.84,1260.98 2601.92,1261.06 2601.92,1276.57 2613.07,1287.72 v1(2613.07,1288.04)
LIN_VDD: C123.1 D8.2 R31.2 R32.2 U23.7 | length 277.6
  Top Layer w15: v1(2691.48,1338.07) 2690.91,1337.49 2654.72,1337.49 2635,1357.22 D8.2@2635,1404.22 2637.52,1406.74 C123.1@2744.38,1406.74 2744.54,1406.58 2744.54,1351.76 U23.7@2744.7,1351.6
LVDS_CLK_RTC_CLKIN_TP: U1.L4 U15.10 | length 1648.5
  Top Layer w4: -588.77,951.44 -589.23,951.44 -596.1,944.56 -596.1,885.75 -566.61,856.26 U1.L4@-546.24,856.26
  Top Layer w5.9: -588.77,951.44 -193.32,951.44 -155,913.12 -155,851.03 -147.29,843.32 41,843.32 66.9,869.22 66.9,1013.78 66.9,1234.03 117.91,1285.05 169.52,1285.05 181.34,1296.87 251.62,1296.87 338.26,1210.23 345.07,1210.23 349.26,1214.42 349.26,1227.16 356.55,1234.45 392.39,1234.45 U15.10@392.51,1234.56
LVDS_D0_LIN_PHY_RX: U1.H2 U15.12 | length 1646.1
  Top Layer w4: U1.H2@-506.87,797.2 -495.26,785.59 -416.4,785.59
  Top Layer w5.9: -416.4,785.59 -398.37,767.56 -371.74,767.56 -357.03,782.27 -357.03,902.96 -338.46,921.54 -307.86,921.54 -289.9,903.57 -289.9,847.78 -243.77,801.66 -171.95,801.66 -141.18,832.42 41.69,832.42 62.42,811.68 83.29,811.68 93.59,821.99 93.59,868.74 78.8,883.53 78.8,1013.78 78.8,1226.97 124.98,1273.15 174.45,1273.15 186.27,1284.97 243.19,1284.97 344.79,1183.38 U15.12@392.51,1183.38
LVDS_D1_XDS_UARTA_RX_CAN_RX: U1.J3 U15.6 | length 1646.2
  Top Layer w4: -608.41,982.54 -623.12,967.84 -623.12,874.62 -576.36,827.82 -537.49,827.82 U1.J3@-526.56,816.89
  Top Layer w5.9: -608.41,982.54 -118.26,982.54 -109.31,973.6 -109.31,918.56 -104.97,914.22 -95.57,914.22 -90.08,919.72 -90.08,972.37 -79.01,983.44 11.9,983.44 31.2,1002.74 31.2,1013.78 31.2,1249.05 102.89,1320.75 154.73,1320.75 170.91,1336.92 U15.6@392.51,1336.92
LVDS_D2_XDS_UARTA_TX_CAN_TX: U1.K3 U15.7 | length 1646.4
  Top Layer w4: -603.27,971.24 -613.08,961.42 -613.08,877.28 -579.85,844.05 -572.38,836.57 U1.K3@-526.56,836.57
  Top Layer w5.9: -603.27,971.24 -134.3,971.24 -124.23,961.16 -124.23,889.79 -113.6,879.16 -61.43,879.16 -51.96,888.63 -51.96,951.49 -29.91,973.54 19.26,973.54 43.1,997.37 43.1,1013.78 43.1,1244.13 107.82,1308.85 159.66,1308.85 172.84,1322.03 328.71,1322.03 339.41,1311.33 U15.7@392.51,1311.33
LVDS_D3_nERROR_LED_WD_TP: U1.J4 U15.4 | length 1646.4
  Top Layer w4: -614.17,993.34 -634.12,973.4 -634.12,871.47 -581.75,819.1 -550.03,819.1 -547.82,816.89 U1.J4@-546.24,816.89
  Top Layer w5.9: -614.17,993.34 4.95,993.34 19.3,1007.69 19.3,1013.78 19.3,1253.98 97.96,1332.65 149.8,1332.65 166.45,1349.3 191.7,1349.3 219,1376.6 219,1400.9 234.4,1416.31 284.95,1416.31 304,1397.25 304,1357.6 310.31,1351.29 320.78,1351.29 357.59,1388.09 U15.4@392.51,1388.1
LVDS_FRCLK_HOST_CLK_TP: U1.L3 U15.9 | length 1646.7
  Top Layer w4: -596.04,961.34 -604.1,953.27 -604.1,881.02 -567.65,844.57 -538.24,844.57 U1.L3@-526.56,856.26
  Top Layer w5.9: -596.03,961.34 -175.68,961.34 -137,922.66 -137,878.8 -120.03,861.83 27.25,861.83 55,889.58 55,1013.78 55,1239.2 112.75,1296.95 164.59,1296.95 176.41,1308.77 287.05,1308.77 335.67,1260.15 U15.9@392.51,1260.15
MODE: Q3.3 R238.2 R244.2 U19.3 U20.3 | length 1760.9
  Top Layer w5.9: Q3.3@1265,364.24 1265,429.6 1284.79,449.39 1334.3,449.39 v1(1356.41,471.49)
  Int2 (PWR) w5.9: v1(1356.41,471.49) 1400.36,427.54 1468.03,427.54 1507.31,466.82 1538.28,466.82 1593.44,411.65 1624.15,411.65 1728.9,516.4 1849.43,516.4 1870.27,495.56 2313.95,495.56 2375.83,557.43 2531.9,557.43 v1(2587.28,502.04)
  Bottom Layer w5.9: U19.3@1330.05,418.35 1330.05,454.1 R238.2@1327.56,456.59 1334.12,463.15 1349.39,463.15 1356.41,470.16 v1(1356.41,471.49) ; R244.2@2508.26,496.28 2513.53,501.55 2526.64,501.55 2535.27,510.17 2577.78,510.17 2585.91,502.04 v1(2587.28,502.04) ; U20.3@2508.43,463.02 2508.43,496.28 R244.2@2509.98,496.28
MUX_CTRL_FTDI_DCA_SPI: R12.2 S4.3 U28.14 U28.24 | length 1510.3
  Top Layer w5.9: v1(708.74,1425.77) 764.98,1425.77 789.77,1400.98 789.77,1334.41 763.38,1308.03 729.33,1308.03 708.87,1287.57 708.87,1142.7 687.22,1121.05 687.22,1070.09 761.85,995.46 761.85,668.34 768.83,661.36 S4.3@799.68,661.36
  Bottom Layer w5.9: R12.2@354.19,1407.57 417.04,1407.57 ; U28.14@427.49,1460.36 427.49,1418.01 417.04,1407.57 ; U28.24@683.27,1460.25 683.27,1423.89 686.73,1420.43 700.12,1420.43 705.47,1425.77 v1(708.74,1425.77) 707.46,1424.5 707.46,1413.61 702.3,1408.44 620.5,1408.44 566.08,1354.02 441.75,1354.02 417.04,1378.74 417.04,1407.57
MUX_CTRL_LVDS_UART_CAN_TP: R90.2 S1.3 U15.14 U15.24 | length 1363.2
  Top Layer w5.9: v1(496.51,1126.96) 496.51,1315.35 539.95,1358.79 539.95,1424.15 580.68,1464.88 U15.24@620.85,1464.88 668.9,1464.88 675.8,1471.78 675.8,1486.74 R90.2@676.08,1487.02 ; U15.14@620.85,1208.97 665.44,1208.97 681.74,1192.67 681.74,1173.85 660.24,1152.35 660.24,1136.29 v1(658.45,1134.5) ; S1.3@873.96,1032.62 930.61,1032.62 962.33,1000.89 979.85,1000.89 1006.61,1027.65 1006.61,1059.3 v1(969.1,1096.82)
  Int2 (PWR) w5.9: v1(496.51,1126.96) 514.59,1145.04 600.32,1145.04 610.86,1134.5 v1(658.45,1134.5) ; v1@658.51,1134.5 707.09,1134.5 718.99,1122.6 863.52,1122.6 889.3,1096.82 v1(969.1,1096.82)
MUX_CTRL_RS232: R7.1 S1.4 U12.16 | length 864.2
  Top Layer w5.9: S1.4@873.96,982.62 922.29,982.62 943.13,961.78 943.13,864.83 960.93,847.02 1194.4,847.02 1207.64,860.26 1207.64,964.58 1247.05,1004 1330.92,1004 v1@1375.49,1048.56
  Bottom Layer w5.9: v1(1375.49,1048.9) 1375.49,1067.43 1378.95,1070.89 R7.1@1410.82,1070.89 1413.07,1068.64 U12.16@1459.67,1068.64
MUX_CTRL_SPI_I2C_MODE: R27.1 S1.6 U24.15 | length 1036.1
  Top Layer w5.9: v1(728.01,1140.55) 709.9,1122.44 709.63,1122.44 699.12,1111.92 699.12,1075.02 780.24,993.89 780.24,922.21 819.84,882.62 S1.6@873.96,882.62
  Int2 (PWR) w5.9: v1(321.51,1176.36) 364.06,1176.36 381.6,1158.82 381.6,1125.68 396.17,1111.12 468.44,1111.12 477.95,1120.63 477.95,1133.95 500.94,1156.94 711.62,1156.94 v1(728.01,1140.55)
  Bottom Layer w5.9: U24.15@208.28,1143.67 208.28,1170.46 224.42,1186.6 R27.1@253.02,1186.6 ; R27.1@252.85,1186.43 252.85,1167.67 259.84,1160.68 306.49,1160.68 321.51,1175.7 v1(321.51,1176.36)
MUX_CTRL_UARTA_CAN: R8.1 S1.5 U12.8 | length 1323.5
  Top Layer w5.9: S1.5@873.96,932.62 905.84,932.62 922.76,915.7 922.76,861.86 949.5,835.12 1202.38,835.12 1220.06,852.8 1220.06,960.18 1251.47,991.59 1390.49,991.59 1447.03,935.05 1499.71,935.05 1549.16,984.49 1549.16,998.15 v1(1548.79,998.52)
  Bottom Layer w5.9: v1(1548.79,998.52) 1548.79,875.98 1567.75,857.01 1617.63,857.01 1623.48,851.16 R8.1@1692.31,851.16 ; U12.8@1691.95,889.51 1726.34,889.51 1735.86,879.99 1735.86,861.03 1726.35,851.52 R8.1@1692.31,851.52
MUX_CTRL_XDS_DCA_JTAG: R5.1 S1.2 U4.15 | length 1459.3
  Top Layer w5.9: v1(227.33,870.46) 225.01,872.77 225.01,887.35 220.65,891.71 206.71,891.71 R5.1@205.72,890.72 205.72,865.15 215.6,855.27 250.52,855.27 261.97,843.82 U4.15@261.97,811.41 ; S1.2@873.96,1082.62 907.62,1082.62 915.91,1090.9 v1@915.91,1234.24
  Int2 (PWR) w5.9: v1(227.33,870.46) 229.53,872.66 229.53,1018.89 181.27,1067.15 181.27,1138.49 204.18,1161.41 204.18,1185.82 261.27,1242.9 770.85,1242.9 807.86,1205.89 887.41,1205.89 v1(915.83,1234.31)
nERROR_LED_WD_TP: D9.2 R65.2 TP2.1 U15.2 | length 734.5
  Top Layer w5.9: U15.2@392.51,1439.28 TP2.1@342.51,1439.28 342.51,1473.44 353.74,1484.67 555.99,1484.67 609.69,1538.38 734.78,1538.38 801.72,1471.44 R65.2@884.63,1471.44 884.63,1444.74 890.63,1438.74 D9.2@890.63,1420.33
NET_SOP1: R207.2 S1.1 | length 77.7
  Top Layer w6: R207.2@823.96,1165.62 824.35,1165.23 865.34,1165.23 873.96,1156.61 S1.1@873.96,1132.62
NetC37_2: C37.2 R69.1 U5.3 | length 197.3
  Top Layer w5.9: U5.3@2415.27,1134.88 2415.27,1178.88 2425.51,1189.11 C37.2@2516.95,1189.11 2516.95,1216.64 2513.5,1220.09 2507.71,1220.09 2501.31,1226.5 R69.1@2501.31,1226.67
NetC39_2: C39.2 R68.1 R79.2 | length 69.2
  Top Layer w5.9: C39.2@2389.31,1433.6 2388.47,1432.76 R68.1@2388.47,1401.45 R79.2@2425.19,1401.45
NetC48_1: C48.1 C63.1 D4.1 F1.1 FB1.1 FB2.1
NetC94_1: C94.1 R169.1 U21.96 | length 285.3
  Bottom Layer w5.9: U21.96@2527.55,630.36 2701.41,630.36 2716.51,615.25 2765.08,615.25 R169.1@2766.02,614.32 2766.02,579.24 C94.1@2762.38,575.6
NetC95_2: C95.2 R202.2 U21.68 | length 133.2
  Bottom Layer w5.9: U21.68@2527.55,1071.3 2527.81,1071.57 2557.19,1071.57 2580.64,1095.03 C95.2@2599.45,1095.03 2632.49,1095.03 2644.1,1083.42 R202.2@2644.1,1081.45
NetC97_2: C97.2 U21.89 Y2.3 | length 154.3
  Bottom Layer w5.9: U21.89@2527.55,740.59 2588.52,740.59 2601.74,727.38 2616.04,727.38 C97.2@2616.98,726.44 2648.97,726.44 2665.26,710.15 Y2.3@2665.26,706.21
NetC98_2: C98.2 U21.88 Y2.1 | length 257.3
  Bottom Layer w5.9: U21.88@2527.55,756.34 2587.42,756.34 2599.35,768.27 C98.2@2616.98,768.27 2616.98,766.3 2629.78,753.5 2724.52,753.5 2736.13,765.11 Y2.1@2736.13,796.76
NetC99_2: C99.2 C102.2 R233.1 U21.9 U22.1 | length 805.4
  Int2 (PWR) w5.9: v1(1806.97,362.47) 1806.97,390.58 1834.99,418.6 v1(1854.03,418.58)
  Bottom Layer w5.9: C102.2@1719.12,513.92 C99.2@1759.12,513.92 1759.26,513.77 1776.32,513.77 1786.25,503.84 1786.25,395.36 1806.34,375.28 1806.34,363.11 v1(1806.97,362.47) ; v1@1854.43,418.58 1874,418.58 1915.78,460.36 U22.1@1935.4,460.36 1935.4,495 1946.62,506.22 R233.1@1990,506.22 1989.32,506.9 1989.32,527.37 1982.52,534.17 1967.65,534.17 1956.76,545.06 1956.76,751.3 1951.72,756.34 U21.9@1921.25,756.34
NetC158_1: C158.1 R259.1 U29.6 | length 42.6
  Top Layer w10: U29.6@2920.73,652.78 2922.7,652.78 2928.15,658.22 C158.1@2961.03,658.22
NetD1_2: D1.2 L9.2
NetD2_2: D2.2 FB1.2 FB2.2
NetD3_1: D3.1 R172.1 | length 86.8
  Top Layer w5.9: R172.1@1308.56,781.11 1335.39,781.11 1361.24,806.97 D3.1@1361.24,830.33
NetD3_2: D3.2 Q2.3 | length 71.2
  Top Layer w5.9: Q2.3@1290.91,889.63 1293.22,887.32 D3.2@1361.15,887.32
NetD5_1: D5.1 R141.1 | length 35.1
  Top Layer w5.9: R141.1@592.31,169 R141.1@592.69,169.38
  Top Layer w8: R141.1@592.69,169.38 D5.1@592.69,203.96
NetD5_2: D5.2 Q1.3 | length 108
  Top Layer w8: Q1.3@541.43,258.24 541.43,273.65 551.95,284.17 579.4,284.17 592.69,270.87 D5.2@592.69,239.4
NetD6_1: D6.1 R174.1 | length 90.6
  Top Layer w5.9: R174.1@387.71,132.35 387.71,78.02 394.04,71.69 D6.1@421.36,71.69
NetD7_1: D7.1 R28.1 | length 28.6
  Top Layer w5.9: R28.1@1119.03,151 1119.22,150.81 D7.1@1119.22,122.48
NetD7_2: D7.2 Q4.3 | length 46.1
  Top Layer w5.9: D7.2@1154.65,122.48 1154.65,100.77 1158.55,96.87 Q4.3@1158.55,78
NetD8_1: D8.1 R21.2 | length 97
  Top Layer w15: D8.1@2635,1230.99 2638.08,1234.07 v1(2694.83,1234.07)
  Bottom Layer w15: v1(2694.83,1234.07) 2695.4,1234.64 2695.4,1236.55 2699.62,1240.77 2699.62,1262.1 R21.2@2703.76,1266.23
NetD9_1: D9.1 R64.1 | length 42.2
  Top Layer w5.9: R64.1@925.84,1462.47 926.06,1462.24 D9.1@926.06,1420.33
NetD10_1: D10.1 R252.2 | length 40.7
  Top Layer w5.9: R252.2@1427.2,841.15 1427.86,840.49 D10.1@1427.86,800.77
NetD12_2: D12.2 L8.2
NetF1_2: F1.2 J7.1
NetJ6_4: J6.4 R34.1 | length 121.9
  Bottom Layer w5.9: R34.1@811.41,1218.36 829.69,1218.36 839.14,1208.91 839.14,1193.42 850.01,1182.55 J6.4@909.41,1182.55
NetJ6_5: J6.5 R37.2 | length 98.8
  Bottom Layer w5.9: J6.5@1135,1162.86 1194.13,1162.86 1221.84,1190.57 R37.2@1221.84,1191.07
NetJ6_6: J6.6 R38.1 | length 162
  Bottom Layer w5.9: R38.1@782.6,1218.59 782.6,1198 793.24,1187.36 824.44,1187.36 848.93,1162.86 J6.6@909.41,1162.86
NetJ6_7: J6.7 R39.2 | length 90.4
  Bottom Layer w5.9: J6.7@1135,1143.18 1192.58,1143.18 1201.27,1151.87 R39.2@1221.84,1151.87
NetJ6_8: J6.8 R40.1 | length 100.7
  Bottom Layer w5.9: R40.1@814.33,1156.72 830.47,1156.72 844.02,1143.18 J6.8@909.41,1143.18
NetJ6_9: J6.9 R41.2 | length 91.3
  Bottom Layer w5.9: J6.9@1135,1123.49 1193.11,1123.49 1203.92,1112.68 R41.2@1221.84,1112.68
NetJ6_10: J6.10 R42.1 | length 95.1
  Bottom Layer w5.9: R42.1@814.46,1123.93 814.68,1123.71 909.2,1123.71 J6.10@909.41,1123.49
NetJ6_11: J6.11 R52.2 | length 109.4
  Bottom Layer w5.9: J6.11@1135,1103.81 1193.7,1103.81 1203.4,1094.11 1203.4,1076.94 1206.86,1073.49 R52.2@1221.84,1073.49
NetJ6_12: J6.12 R53.1 | length 100
  Bottom Layer w5.9: R53.1@814.52,1091.37 833.76,1091.37 846.21,1103.81 J6.12@909.41,1103.81
NetJ6_13: J6.13 R58.2 | length 126.7
  Bottom Layer w5.9: J6.13@1135,1084.12 1185.17,1084.15 1189.98,1079.35 1189.98,1046.61 1202.3,1034.29 R58.2@1221.84,1034.29
NetJ6_26: J6.26 R219.1 | length 86.2
  Bottom Layer w4: R219.1@829.41,971.01 829.41,970.52 838.5,961.43 865.64,961.43 870.22,966.01 J6.26@909.41,966.01
NetJ6_28: J6.28 R220.1 | length 86.6
  Bottom Layer w4: R220.1@829.41,941.33 829.41,941.82 839.02,951.43 865.12,951.43 870.22,946.33 J6.28@909.41,946.33
NetJ6_32: J6.32 R221.1 | length 146.4
  Bottom Layer w4: R221.1@769.41,911.96 769.41,911.47 778.76,902.12 857.38,902.12 858.73,903.47 905.92,903.47 J6.32@909.41,906.96
NetJ6_34: J6.34 R222.1 | length 146.4
  Bottom Layer w4: R222.1@769.41,882.27 769.41,882.77 778.76,892.12 857.38,892.12 858.73,890.77 905.92,890.77 J6.34@909.41,887.27
NetJ6_38: J6.38 R223.1 | length 86.2
  Bottom Layer w4: R223.1@829.41,852.9 829.41,852.41 838.5,843.32 865.64,843.32 870.22,847.9 J6.38@909.41,847.9
NetJ6_40: J6.40 R224.1 | length 86.6
  Bottom Layer w4: R224.1@829.41,823.22 829.41,823.71 839.02,833.32 865.12,833.32 870.22,828.22 J6.40@909.41,828.22
NetJ6_44: J6.44 R225.1 | length 156.4
  Bottom Layer w4: R225.1@759.41,793.85 759.41,793.36 768.76,784.01 865.38,784.01 870.22,788.85 J6.44@909.41,788.85
NetJ6_46: J6.46 R226.1 | length 156.4
  Bottom Layer w4: R226.1@759.41,764.16 759.41,764.66 768.76,774.01 865.38,774.01 870.22,769.16 J6.46@909.41,769.16
NetJ6_50: J6.50 R227.1 | length 86.4
  Bottom Layer w4: R227.1@829.41,734.79 829.41,734.3 838.76,724.95 865.38,724.95 870.22,729.79 J6.50@909.41,729.79
NetJ6_51: J6.51 R59.2 | length 105.8
  Bottom Layer w5.9: J6.51@1135,710.11 1186.26,710.11 1192.57,716.41 1192.57,728.81 1202.07,738.31 R59.2@1221.84,738.31
NetJ6_52: J6.52 R228.1 | length 86.4
  Bottom Layer w4: R228.1@829.41,705.11 829.41,705.6 838.76,714.95 865.38,714.95 870.22,710.11 J6.52@909.41,710.11
NetJ6_53: J6.53 R60.2 | length 90.4
  Bottom Layer w5.9: J6.53@1135,690.42 1192.58,690.42 1201.27,699.12 R60.2@1221.84,699.12
NetJ6_55: J6.55 R61.2 | length 91.3
  Bottom Layer w5.9: J6.55@1135,670.74 1193.11,670.74 1203.92,659.92 R61.2@1221.84,659.92
NetJ6_56: J6.56 R229.1 | length 146.4
  Bottom Layer w4: R229.1@769.41,675.74 769.41,675.25 776.76,667.9 777.26,667.9 779.26,665.9 848.35,665.9 865.38,665.9 870.22,670.74 J6.56@909.41,670.74
NetJ6_57: J6.57 R62.2 | length 108.7
  Bottom Layer w5.9: J6.57@1135,651.05 1192.5,651.05 1202.6,640.96 1202.6,625.09 1206.96,620.73 R62.2@1221.84,620.73
NetJ6_58: J6.58 R230.1 | length 146.4
  Bottom Layer w4: R230.1@769.41,646.05 769.41,646.55 776.76,653.9 777.26,653.9 779.26,655.9 844.21,655.9 865.38,655.9 870.22,651.05 J6.58@909.41,651.05
NetJ6_59: J6.59 R63.2 | length 126.6
  Bottom Layer w5.9: J6.59@1135,631.37 1182.56,631.37 1189.87,624.06 1189.87,591.73 1200.52,581.08 R63.2@1221.84,581.08
NetJ10_6: J10.6 J10.7 J10.8 J10.9 J10.10 J10.11 R261.2
NetQ1_1: Q1.1 R171.1 | length 30
  Top Layer w5.9: R171.1@525.69,182.97 Q1.1@525.69,212.97
NetQ2_1: Q2.1 R179.2 | length 111.6
  Top Layer w5.9: R179.2@1263.62,925.75 1265.32,924.05 Q2.1@1265.32,814.83
NetQ3_1: Q3.1 R173.1 R177.2 | length 108.2
  Top Layer w5.9: R177.2@1212.07,280.87 1212.07,297.93 1200.25,309.75 R173.1@1200.25,330.46 1222.97,330.46 1234.46,318.96 Q3.1@1249.25,318.96
NetQ4_1: Q4.1 R66.1 | length 61.3
  Top Layer w5.9: R66.1@1076.68,122.6 1076.68,100.87 1083.81,93.75 Q4.1@1113.28,93.75
NetR2_1: R2.1 R101.2 U6.2 | length 153.5
  Bottom Layer w5.9: U6.2@2510.78,158.73 2513.03,156.47 2542.54,156.47 2549.88,149.14 2549.88,72.65 R101.2@2549.02,71.79 R2.1@2549.02,39.05
NetR6_2: R6.2 U4.13 | length 235.5
  Top Layer w5.9: R6.2@293,1010.98 293.21,1010.77 310.2,1010.77 324.55,996.42 324.55,876.93 v1(307.62,860) 307.62,858.02 293.47,843.87 U4.13@293.47,811.41
NetR13_2: R13.2 R203.2 SW1.2 | length 249.7
  Top Layer w5.9: SW1.2@1396.77,212.35 1396.77,182.62 1409.69,169.71 1485.34,169.71 1515.94,139.1 R203.2@1563.73,139.1 R13.2@1563.73,104.1
NetR14_1: R14.1 R103.2 U6.1 | length 281.5
  Bottom Layer w5.9: U6.1@2510.78,178.41 2547.74,178.41 2563.68,162.47 2563.68,114.5 2581.67,96.52 2670.71,96.52 2677.68,89.55 R14.1@2677.68,39.82
NetR16_2: R16.2 R206.2 R207.1 R208.2 | length 127.2
  Top Layer w5.9: R206.2@783.3,1115.15 785.27,1115.15 799.51,1129.39 R208.2@819.66,1129.39 ; R16.2@784.33,1201.3 784.33,1165.88 R207.1@784.59,1165.62 R206.2@784.59,1116.44
NetR18_2: R18.2 U23.1 | length 140.4
  Top Layer w5.9: v1(2640.07,1288.88) 2640.35,1288.6 2707.3,1288.6 2719.11,1276.8 U23.1@2719.11,1249.24
  Bottom Layer w5.9: v1(2640.07,1288.88) 2641.14,1287.82 2641.14,1262.05 R18.2@2642.2,1260.98
NetR19_2: R19.2 U23.4 | length 140
  Top Layer w5.9: U23.4@2795.88,1249.24 2795.88,1281.65 2805.38,1291.16 v1(2805.62,1291.16)
  Bottom Layer w5.9: R19.2@2760.28,1225.35 2776.11,1225.35 2805.62,1254.86 v1(2805.62,1291.16)
NetR25_1: R25.1 U6.5 | length 83.7
  Bottom Layer w5.9: R25.1@2477.18,55.6 2477.18,73.67 2470.87,79.98 2470.87,94.72 2475.82,99.67 U6.5@2510.78,99.67
NetR29_1: R29.1 U6.4 | length 152.7
  Bottom Layer w5.9: R29.1@2442.08,222.2 2442.08,151.44 2474.16,119.36 U6.4@2510.78,119.36
NetR33_2: R33.2 U24.13 | length 144.7
  Top Layer w5.9: v1(147.43,1200.04) 162.59,1200.04 180.11,1182.52 R33.2@180.11,1156.14
  Bottom Layer w5.9: v1(147.43,1200.04) 164.32,1200.04 176.78,1187.57 U24.13@176.78,1143.67
NetR45_1: R45.1 U2.5 | length 141.1
  Top Layer w5.9: R45.1@-203.66,591.06 -186.35,591.06 -159.4,564.1 v1(-98.28,564.1)
  Bottom Layer w5.9: U2.5@-98.86,588.39 -98.41,587.94 -98.41,564.23 v1(-98.28,564.1)
NetR46_2: R46.2 U2.2 | length 138
  Bottom Layer w6: R46.2@-222.82,676.58 -222.82,657.38 -217.43,652 -193,652 -171.8,673.2 -142.8,673.2 -137.9,678.1 U2.2@-137.9,698.95
NetR47_2: R47.2 U2.3 | length 158.8
  Bottom Layer w5.9: R47.2@-239.59,642.85 -234.53,637.78 -188.25,637.78 -162.79,663.25 -136.81,663.25 -118.22,681.85 U2.3@-118.22,698.95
